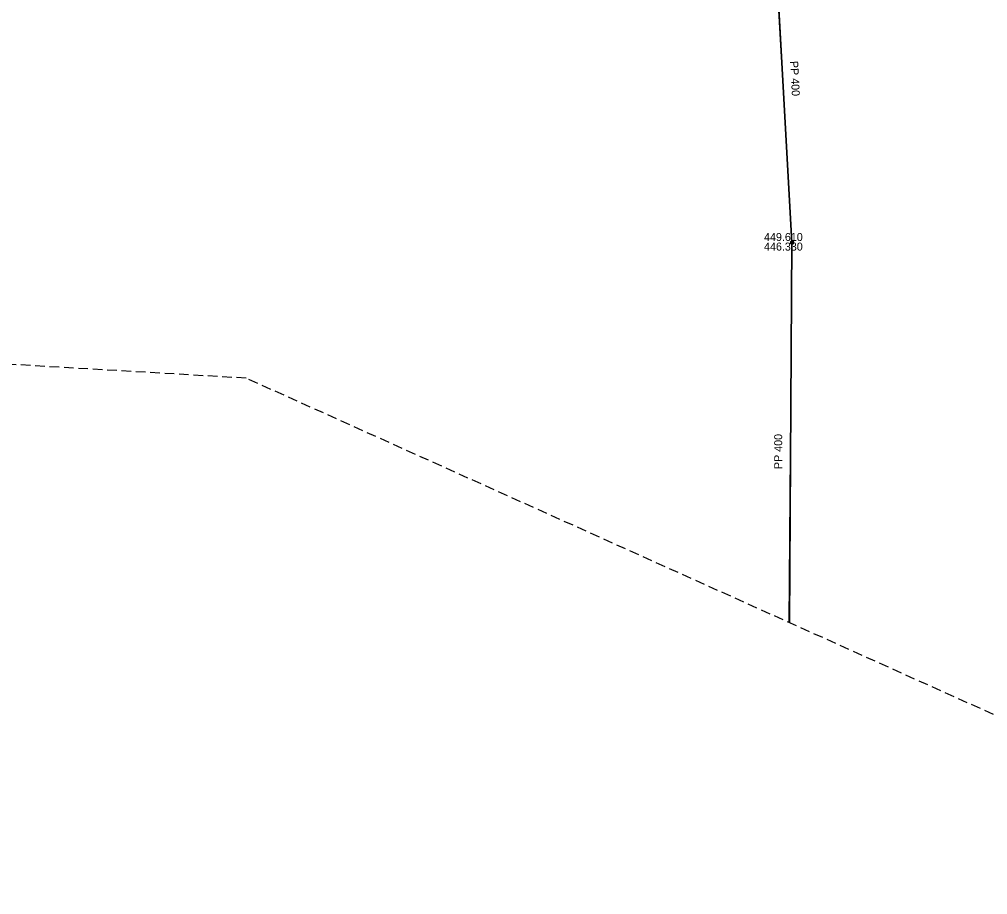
# Model space of a CAD drawing. Extents: x -873619 to -867639, y -1015082 to -1012326.
# Drawn here: x -873315.2 to -873182.1, y -1014330.1 to -1014209.8 of the extents above; entities that cross this region are included whole.
import ezdxf

# ---------------------------------------------------------------- set-up
doc = ezdxf.new("R2010")
doc.units = 0
doc.header["$LTSCALE"] = 0.44
doc.linetypes.add('MEDIUM_DASHED', pattern=[4.5, 3, -1.5])
for name, color, linetype, lineweight in [('1', 7, 'Continuous', 13), ('21', 7, 'Continuous', 35), ('3', 7, 'Continuous', 25), ('32', 7, 'Continuous', 13), ('62', 7, 'MEDIUM_DASHED', 25)]:
    doc.layers.add(name, color=color, linetype=linetype, lineweight=lineweight)

msp = doc.modelspace()

# ---------------------------------------------------------------- linework, layer by layer
at = {"layer": '21'}
for p, q in [((-873211.46, -1014197.31), (-873209.01, -1014240.45)), ((-873209.01, -1014240.45), (-873209.338, -1014292.699))]:
    msp.add_line(p, q, dxfattribs=at)
at = {"layer": '3'}
msp.add_lwpolyline([(-873209.421, -1014292.661), (-873208.998, -1014240.45), (-873211.448, -1014197.31), (-873215.58, -1014166.03), (-873205.44, -1014160.07), (-873195.92, -1014151.84), (-873190.998, -1014149.15), (-873189.02, -1014105.45), (-873184.64, -1014067), (-873178.998, -1014022.35), (-873173.208, -1014002.85), (-873150.578, -1013958.19), (-873123.56, -1013906.71), (-873116.49, -1013857.17), (-873096.298, -1013812.05), (-873076.908, -1013772.84), (-873099.08, -1013724.68), (-873112.568, -1013694.19), (-873154.458, -1013666.63), (-873180.788, -1013644.59), (-873224.641, -1013607.538), (-873251.958, -1013559.37), (-873281.448, -1013506.61), (-873307.717, -1013457.772)], dxfattribs=at)
at = {"layer": '32'}
for points in [[(-873208.769, -1014240.45), (-873208.775, -1014240.398), (-873208.792, -1014240.348), (-873208.821, -1014240.304), (-873208.858, -1014240.267), (-873208.903, -1014240.24), (-873208.953, -1014240.223), (-873209.006, -1014240.219), (-873209.058, -1014240.226), (-873209.107, -1014240.245), (-873209.15, -1014240.274), (-873209.186, -1014240.313), (-873209.212, -1014240.358), (-873209.228, -1014240.409), (-873209.231, -1014240.461), (-873209.223, -1014240.513), (-873209.203, -1014240.562), (-873209.172, -1014240.605), (-873209.133, -1014240.639), (-873209.087, -1014240.665), (-873209.036, -1014240.679), (-873208.983, -1014240.681), (-873208.932, -1014240.671), (-873208.884, -1014240.65), (-873208.841, -1014240.619), (-873208.807, -1014240.578), (-873208.783, -1014240.532), (-873208.771, -1014240.481)], [(-873208.799, -1014240.45), (-873208.805, -1014240.401), (-873208.822, -1014240.355), (-873208.85, -1014240.315), (-873208.887, -1014240.283), (-873208.931, -1014240.261), (-873208.979, -1014240.25), (-873209.028, -1014240.25), (-873209.075, -1014240.263), (-873209.118, -1014240.287), (-873209.154, -1014240.32), (-873209.181, -1014240.361), (-873209.197, -1014240.408), (-873209.201, -1014240.457), (-873209.194, -1014240.505), (-873209.175, -1014240.55), (-873209.145, -1014240.59), (-873209.107, -1014240.621), (-873209.063, -1014240.641), (-873209.015, -1014240.651), (-873208.966, -1014240.649), (-873208.919, -1014240.634), (-873208.876, -1014240.609), (-873208.842, -1014240.575), (-873208.816, -1014240.533), (-873208.802, -1014240.486)], [(-873208.829, -1014240.45), (-873208.835, -1014240.405), (-873208.852, -1014240.363), (-873208.88, -1014240.328), (-873208.916, -1014240.301), (-873208.958, -1014240.284), (-873209.003, -1014240.279), (-873209.048, -1014240.285), (-873209.089, -1014240.304), (-873209.124, -1014240.332), (-873209.151, -1014240.369), (-873209.167, -1014240.411), (-873209.171, -1014240.456), (-873209.164, -1014240.501), (-873209.145, -1014240.542), (-873209.116, -1014240.576), (-873209.079, -1014240.602), (-873209.036, -1014240.618), (-873208.991, -1014240.621), (-873208.946, -1014240.613), (-873208.906, -1014240.593), (-873208.872, -1014240.564), (-873208.846, -1014240.526), (-873208.832, -1014240.483)], [(-873208.859, -1014240.45), (-873208.864, -1014240.409), (-873208.882, -1014240.372), (-873208.909, -1014240.341), (-873208.944, -1014240.32), (-873208.984, -1014240.309), (-873209.025, -1014240.311), (-873209.064, -1014240.324), (-873209.098, -1014240.348), (-873209.123, -1014240.38), (-873209.138, -1014240.418), (-873209.141, -1014240.459), (-873209.133, -1014240.499), (-873209.113, -1014240.535), (-873209.084, -1014240.564), (-873209.047, -1014240.583), (-873209.007, -1014240.591), (-873208.966, -1014240.587), (-873208.928, -1014240.572), (-873208.896, -1014240.546), (-873208.873, -1014240.512), (-873208.86, -1014240.473)], [(-873208.889, -1014240.45), (-873208.894, -1014240.414), (-873208.912, -1014240.382), (-873208.938, -1014240.357), (-873208.972, -1014240.342), (-873209.008, -1014240.339), (-873209.043, -1014240.347), (-873209.074, -1014240.367), (-873209.097, -1014240.395), (-873209.11, -1014240.429), (-873209.11, -1014240.466), (-873209.099, -1014240.501), (-873209.078, -1014240.53), (-873209.048, -1014240.551), (-873209.013, -1014240.561), (-873208.976, -1014240.559), (-873208.942, -1014240.545), (-873208.915, -1014240.522), (-873208.896, -1014240.49), (-873208.889, -1014240.455)], [(-873208.919, -1014240.45), (-873208.924, -1014240.419), (-873208.941, -1014240.393), (-873208.967, -1014240.376), (-873208.997, -1014240.369), (-873209.028, -1014240.373), (-873209.055, -1014240.39), (-873209.073, -1014240.414), (-873209.081, -1014240.445), (-873209.077, -1014240.475), (-873209.062, -1014240.503), (-873209.038, -1014240.522), (-873209.008, -1014240.531), (-873208.977, -1014240.528), (-873208.949, -1014240.514), (-873208.929, -1014240.49), (-873208.919, -1014240.461)], [(-873208.949, -1014240.45), (-873208.954, -1014240.426), (-873208.971, -1014240.408), (-873208.994, -1014240.399), (-873209.018, -1014240.402), (-873209.039, -1014240.416), (-873209.05, -1014240.438), (-873209.05, -1014240.463), (-873209.038, -1014240.484), (-873209.018, -1014240.498), (-873208.993, -1014240.501), (-873208.97, -1014240.492), (-873208.954, -1014240.474)], [(-873208.979, -1014240.45), (-873208.984, -1014240.435), (-873208.999, -1014240.429), (-873209.014, -1014240.433), (-873209.021, -1014240.447), (-873209.017, -1014240.462), (-873209.004, -1014240.471), (-873208.989, -1014240.468), (-873208.979, -1014240.456)]]:
    msp.add_lwpolyline(points, close=True, dxfattribs=at)
at = {"layer": '62'}
msp.add_lwpolyline([(-873556.163, -1013770.63), (-872990.942, -1013058.87), (-872369.897, -1012591.341), (-871448.796, -1012465.737), (-870583.52, -1012702.99), (-868999.506, -1012326.176), (-868524.999, -1012528.539), (-868252.856, -1012577.385), (-867687.635, -1012737.88), (-867638.789, -1013044.914), (-867827.196, -1013184.475), (-868176.097, -1013763.652), (-868434.285, -1014335.85), (-868650.604, -1014635.906), (-869550.77, -1014963.874), (-870206.706, -1015082.5), (-871092.916, -1015026.676), (-871923.303, -1014566.126), (-872607.15, -1014370.741), (-872865.338, -1014447.499), (-873284.02, -1014259.092), (-873402.646, -1014252.114), (-873618.965, -1014280.026)], close=True, dxfattribs=at)

# ---------------------------------------------------------------- texts
at = {"layer": '1'}
for rotation, p in [(273, (-873209.273, -1014215.519)), (90, (-873210.354, -1014271.577))]:
    msp.add_text('PP 400', height=1.1, rotation=rotation, dxfattribs=at).set_placement(p)
for s, p in [('449.610 ', (-873212.85, -1014240.23)), ('446.330 ', (-873212.85, -1014241.55))]:
    msp.add_text(s, height=1.1, dxfattribs=at).set_placement(p)

doc.saveas('drawing.dxf')
